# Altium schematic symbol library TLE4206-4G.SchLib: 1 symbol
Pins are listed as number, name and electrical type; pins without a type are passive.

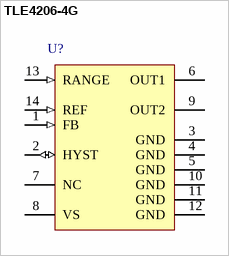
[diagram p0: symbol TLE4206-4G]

## TLE4206-4G
designator U?
H-Bridge Driver Headlight Beam Controller, -40 to 150 degC, PG-DSO-14-22, Reel, Green; Manufacturer: Infineon; PartNumber: TLE4206-4G; Green: TRUE; Group: Servo Driver; Inhibit: FALSE; IPeak: 2 x 1 A; Iq: 2 x 0.8 A; Iq (typ): 10 uA; Protect: short circuit e.a.
footprint INF-PG-DSO-14-22_N (SOP, 14-Leads, Body 8.65x3.9mm, Pitch 1.27mm, IPC Medium Density)
footprint INF-PG-DSO-14-22_L (SOP, 14-Leads, Body 8.65x3.9mm, Pitch 1.27mm, IPC High Density)
footprint INF-PG-DSO-14-22_M (SOP, 14-Leads, Body 8.65x3.9mm, Pitch 1.27mm, IPC Low Density)
pins: 1 FB (in) "Feedback Input", 2 HYST (io) "Hysteresis I/O", 3 GND (power) "Ground", 4 GND (power) "Ground", 5 GND (power) "Ground", 6 OUT1 (power) "Power Output 1", 7 NC "Not connected", 8 VS (power) "Power Supply Voltage", 9 OUT2 (power) "Power Output 2", 10 GND (power) "Ground", 11 GND (power) "Ground", 12 GND (power) "Ground", 13 RANGE (in) "Range Input", 14 REF (in) "Reference Input"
